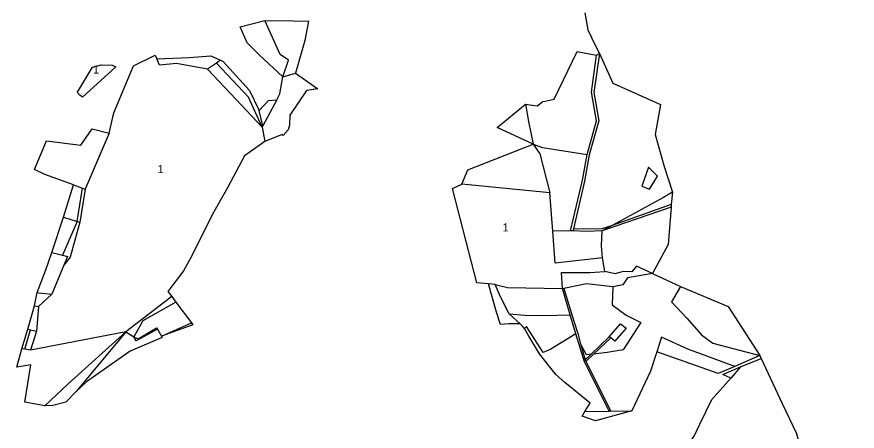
# Model space of a CAD drawing. Extents: x -790696 to -787271, y -1142331 to -1139378.
# Drawn here: x -788575 to -787277, y -1141090 to -1140449 of the extents above; entities that cross this region are included whole.
import ezdxf

# ---------------------------------------------------------------- set-up
doc = ezdxf.new("R2010")
doc.units = 0
for name, color, linetype in [('NERES_HRA', 7, 'Continuous'), ('NERES_SET', 7, 'Continuous'), ('OVNE_SET', 7, 'Continuous'), ('OZN', 7, 'Continuous')]:
    doc.layers.add(name, color=color, linetype=linetype)

msp = doc.modelspace()

# ---------------------------------------------------------------- linework, layer by layer
at = {"layer": 'NERES_HRA'}
for p, q in [((-788354.9, -1140523.9), (-788358.9, -1140514)), ((-788164.4, -1140542.2), (-788155.5, -1140516.4)), ((-788164.4, -1140542.2), (-788144.7, -1140536.2)), ((-788196, -1140619.7), (-788191.9, -1140641.9)), ((-788432.4, -1140629), (-788469.5, -1140715.6)), ((-788487.3, -1140709.1), (-788473.6, -1140714.3)), ((-787836.4, -1140862.9), (-787846.3, -1140861.9)), ((-788557.9, -1140932.2), (-788553.7, -1140933.2)), ((-788358, -1140932.3), (-788351.5, -1140943.1)), ((-788351.5, -1140943.1), (-788305.5, -1140922.2)), ((-787788.1, -1140928), (-787791, -1140930.9)), ((-788406.5, -1140936.4), (-788394.2, -1140943.7)), ((-787695.1, -1140971.6), (-787704.3, -1140955)), ((-788562.6, -1140963.1), (-788567.5, -1140962.3)), ((-787688, -1140970.8), (-787695.1, -1140971.6)), ((-787457.2, -1140990.4), (-787472.2, -1141007.9)), ((-787697.5, -1141059.4), (-787660.1, -1141058.9)), ((-787657.5, -1141058.8), (-787625.2, -1141058.6))]:
    msp.add_line(p, q, dxfattribs=at)
for points in [[(-788155.5, -1140516.4), (-788168.3, -1140507.7), (-788191.8, -1140454.7)], [(-788260.4, -1140516.5), (-788266.7, -1140521), (-788280.8, -1140530.2), (-788328.2, -1140521.4), (-788354.9, -1140523.9)], [(-787698.5, -1140703.5), (-787715.1, -1140776.8), (-787715.6, -1140780.2), (-787720, -1140780), (-787701.5, -1140701.9), (-787693.9, -1140661.9), (-787679.7, -1140610.2), (-787687.7, -1140565.7), (-787679.9, -1140508.5)], [(-787675.1, -1140506), (-787684.1, -1140566.2), (-787676, -1140609.8), (-787691, -1140662.5), (-787698.5, -1140703.5)], [(-787675.1, -1140506), (-787654.6, -1140552), (-787580.9, -1140585), (-787589.3, -1140631.4), (-787575, -1140680.5), (-787562.6, -1140720.1), (-787576.2, -1140728.8), (-787655.4, -1140771.6), (-787671.3, -1140777.2)], [(-788196, -1140619.7), (-788245.2, -1140567.8), (-788280.8, -1140530.2)], [(-788195.2, -1140618), (-788196, -1140619.7), (-788217, -1140573.4), (-788266.7, -1140521)], [(-788173.7, -1140577.8), (-788195.2, -1140618), (-788200.6, -1140594)], [(-787789.4, -1140584.4), (-787784.8, -1140610.9), (-787777.4, -1140646.3)], [(-787777.4, -1140646.3), (-787767.3, -1140660.9), (-787751.8, -1140721.1), (-787887.7, -1140707.9)], [(-787777.4, -1140646.3), (-787763, -1140651.2), (-787693.9, -1140661.9)], [(-787585.5, -1140695.7), (-787599.6, -1140681.5), (-787609.5, -1140711), (-787598.1, -1140715.7), (-787585.5, -1140695.7)], [(-788481.7, -1140765.7), (-788473.6, -1140714.3), (-788469.5, -1140715.6), (-788477.9, -1140766.5)], [(-787720, -1140780), (-787747.2, -1140780.8), (-787751.8, -1140721.1)], [(-787562.6, -1140720.1), (-787564.2, -1140739.6), (-787655.4, -1140771.6)], [(-787564.2, -1140739.6), (-787564.5, -1140743.5), (-787671, -1140780.1)], [(-787564.5, -1140743.5), (-787569.2, -1140801), (-787593.1, -1140845.8), (-787617.8, -1140834.6), (-787625.4, -1140843.3), (-787638.7, -1140842.9)], [(-788503, -1140759.2), (-788481.7, -1140765.7), (-788504.5, -1140817.8)], [(-788481.7, -1140765.7), (-788477.9, -1140766.5), (-788492.7, -1140820.8), (-788502.4, -1140833.3)], [(-787655.4, -1140771.6), (-787671, -1140780.1), (-787695.9, -1140781), (-787715.6, -1140780.2)], [(-787671.3, -1140777.2), (-787700.3, -1140777.4), (-787715.1, -1140776.8)], [(-787670.7, -1140822), (-787743.6, -1140830), (-787747.2, -1140780.8)], [(-787638.7, -1140842.9), (-787650.8, -1140846.8), (-787667, -1140842.7), (-787670.7, -1140822), (-787672, -1140803.4), (-787671, -1140780.1)], [(-788521.1, -1140813.5), (-788504.5, -1140817.8), (-788496.8, -1140819.9), (-788502.4, -1140833.3), (-788521.2, -1140877.8)], [(-787732.4, -1140869.3), (-787733.8, -1140844.7), (-787689.8, -1140844.5), (-787667, -1140842.7)], [(-787593.1, -1140845.8), (-787631.9, -1140852.6), (-787638.9, -1140863.4), (-787654.6, -1140866.5), (-787695.2, -1140862.2), (-787730, -1140869.1)], [(-787593.1, -1140845.8), (-787550.2, -1140866.2), (-787564, -1140890), (-787540.1, -1140915.2), (-787517.4, -1140940.6), (-787499.9, -1140953.9), (-787427.3, -1140972.9)], [(-787814.5, -1140908.6), (-787828.2, -1140882.1), (-787836.4, -1140862.9), (-787817, -1140867.9), (-787732.4, -1140869.3)], [(-787654.6, -1140866.5), (-787655.7, -1140894.6), (-787633.9, -1140910.4), (-787611.5, -1140921.7), (-787638.6, -1140963.9), (-787663.1, -1140968.3), (-787684.3, -1140970.7)], [(-787550.2, -1140866.2), (-787476.2, -1140897), (-787427.3, -1140972.9)], [(-788543.6, -1140875.3), (-788541, -1140876), (-788521.2, -1140877.8), (-788541.4, -1140897.1)], [(-787711.4, -1140939.3), (-787720.3, -1140909.8), (-787732.4, -1140869.3), (-787730, -1140869.1), (-787714.6, -1140919.5), (-787708.6, -1140938.7), (-787704.3, -1140955), (-787697.1, -1140979.5), (-787696.1, -1140982.3), (-787657.5, -1141058.8), (-787660.1, -1141058.9), (-787698.5, -1140982.4), (-787711.4, -1140939.3)], [(-788335.8, -1140881.8), (-788406.5, -1140936.4), (-788553.8, -1140964.5)], [(-788329.6, -1140890.1), (-788380.4, -1140919.1), (-788394.2, -1140943.7)], [(-788548, -1140895.9), (-788541.4, -1140897.1), (-788544.6, -1140935)], [(-787797.8, -1140923.9), (-787814.5, -1140908.6), (-787790.5, -1140910.7), (-787761.3, -1140910.9), (-787720.3, -1140909.8)], [(-788562.6, -1140963.1), (-788553.7, -1140933.2), (-788544.6, -1140935), (-788553.8, -1140964.5), (-788562.6, -1140963.1)], [(-788394.2, -1140943.7), (-788387.6, -1140947.1), (-788359.1, -1140930.1), (-788358, -1140932.3), (-788390.8, -1140950), (-788394.2, -1140943.7)], [(-787711.4, -1140939.3), (-787750.5, -1140963.1), (-787762, -1140968.2), (-787788.1, -1140928)], [(-787657.7, -1140945.6), (-787660, -1140943.8), (-787642.8, -1140923.9), (-787633.8, -1140930.8), (-787651.3, -1140950.8), (-787657.7, -1140945.6)], [(-788532, -1141050.4), (-788495.7, -1141016.6), (-788406.5, -1140936.4), (-788483.2, -1141028.5)], [(-787697.1, -1140979.5), (-787688, -1140970.8), (-787660, -1140943.8)], [(-787657.7, -1140945.6), (-787684.3, -1140970.7), (-787696.1, -1140982.3)], [(-787466.3, -1140989.7), (-787538.9, -1140963.1), (-787579.3, -1140944.7), (-787586.3, -1140966.9)], [(-787425.3, -1140977.4), (-787392.8, -1141047), (-787370.7, -1141093.6), (-787370.7, -1141094), (-787351.6, -1141159.3), (-787335.8, -1141212.7), (-787393.7, -1141207.1), (-787435.2, -1141202.4), (-787438.7, -1141209.6), (-787454.4, -1141237.5)]]:
    msp.add_lwpolyline(points, dxfattribs=at)
at = {"layer": 'NERES_SET'}
for points in [[(-788191.8, -1140454.7), (-788148.1, -1140455.5), (-788124.3, -1140456.2), (-788130, -1140485.6), (-788144.7, -1140536.2), (-788110.3, -1140560.8), (-788127.9, -1140563.2), (-788153.6, -1140601.1), (-788153.8, -1140616.8), (-788156.2, -1140623.9), (-788163.8, -1140632.7), (-788165.4, -1140631.1), (-788191.9, -1140641.9), (-788223.6, -1140664.1), (-788249.4, -1140712.6), (-788273.2, -1140755.5), (-788304.9, -1140818.6), (-788317.5, -1140841.8), (-788341.7, -1140873.8), (-788335.8, -1140881.8), (-788329.6, -1140890.1), (-788305.5, -1140922.2), (-788303.2, -1140925.3), (-788351.5, -1140943.1), (-788350.4, -1140945.1), (-788400.2, -1140965.9), (-788467.5, -1141013.4), (-788483.2, -1141028.5), (-788499.2, -1141044.8), (-788519.3, -1141049.9), (-788532, -1141050.4), (-788562.6, -1141045.1), (-788553.5, -1140987.3), (-788575.1, -1140990.7), (-788567.5, -1140962.3), (-788557.9, -1140932.2), (-788548, -1140895.9), (-788543.6, -1140875.3), (-788530.2, -1140840.5), (-788521.1, -1140813.5), (-788503, -1140759.2), (-788487.3, -1140709.1), (-788531.9, -1140693.1), (-788547.6, -1140685.3), (-788529.4, -1140640.8), (-788476.1, -1140647.9), (-788458.9, -1140622.4), (-788432.4, -1140629), (-788425.1, -1140597.9), (-788394.8, -1140524.8), (-788361.3, -1140508.5), (-788358.9, -1140514), (-788308.8, -1140511.9), (-788275.4, -1140509.7), (-788260.4, -1140516.5), (-788256.6, -1140518.1), (-788215.7, -1140563.2), (-788200.6, -1140594), (-788186.1, -1140578.7), (-788173.7, -1140577.8), (-788168.7, -1140568.1), (-788164.4, -1140542.2), (-788200.9, -1140507.8), (-788219.4, -1140489.4), (-788230.3, -1140464.5), (-788191.8, -1140454.7)], [(-787427.3, -1140972.9), (-787466.3, -1140989.7), (-787491.8, -1141000.5), (-787586.3, -1140966.9), (-787596.1, -1140996.8), (-787625.2, -1141058.6), (-787681.5, -1141073.9), (-787701.7, -1141066.8), (-787697.5, -1141059.4), (-787692.4, -1141050.9), (-787689.7, -1141046.4), (-787728.6, -1141014.3), (-787742.5, -1141002.4), (-787767.9, -1140970.4), (-787784, -1140942.9), (-787791, -1140930.9), (-787794.3, -1140927), (-787797.8, -1140923.9), (-787814.6, -1140923.6), (-787827.9, -1140924.7), (-787834.2, -1140905.8), (-787846.3, -1140861.9), (-787864.8, -1140860.4), (-787902.2, -1140714.9), (-787887.7, -1140707.9), (-787878.5, -1140685.8), (-787777.4, -1140646.3), (-787833.1, -1140620.2), (-787789.4, -1140584.4), (-787771.2, -1140586.9), (-787762.6, -1140580.4), (-787759.2, -1140579.5), (-787745.2, -1140576.3), (-787709.5, -1140502.7)], [(-787709.5, -1140502.7), (-787679.9, -1140508.5), (-787675.1, -1140506)], [(-788444.8, -1140523.4), (-788427.8, -1140523.8), (-788422.1, -1140526.8), (-788473.4, -1140573.5), (-788477.7, -1140570.2), (-788481.9, -1140565.5), (-788479.8, -1140563.4), (-788458.4, -1140527), (-788444.8, -1140523.4)], [(-787277.1, -1141348.3), (-787289.6, -1141344.9), (-787356.6, -1141300.5), (-787392.7, -1141276.6), (-787454.4, -1141237.5), (-787513.3, -1141205), (-787575.7, -1141142.9), (-787560.3, -1141143.2), (-787528.6, -1141096.6), (-787519.9, -1141078.7), (-787501.4, -1141040.6), (-787472.2, -1141007.9), (-787484.7, -1141002.4), (-787457.2, -1140990.4), (-787425.3, -1140977.4)]]:
    msp.add_lwpolyline(points, dxfattribs=at)
at = {"layer": 'OVNE_SET'}
msp.add_lwpolyline([(-787697.8, -1140443.2), (-787693.2, -1140469.6), (-787681.6, -1140492.9), (-787675.1, -1140506), (-787654.6, -1140552), (-787580.9, -1140585), (-787589.3, -1140631.4), (-787575, -1140680.5), (-787562.6, -1140720.1), (-787564.2, -1140739.6), (-787564.5, -1140743.5), (-787569.2, -1140801), (-787593.1, -1140845.8), (-787550.2, -1140866.2), (-787476.2, -1140897), (-787427.3, -1140972.9), (-787425.3, -1140977.4), (-787392.8, -1141047), (-787370.7, -1141093.6)], dxfattribs=at)

# ---------------------------------------------------------------- texts
at = {"layer": 'OZN'}
for p in [(-788457.3, -1140537), (-788357.6, -1140690.8), (-787824.8, -1140781)]:
    msp.add_text('1', height=12.5, dxfattribs=at).set_placement(p)

doc.saveas('drawing.dxf')
